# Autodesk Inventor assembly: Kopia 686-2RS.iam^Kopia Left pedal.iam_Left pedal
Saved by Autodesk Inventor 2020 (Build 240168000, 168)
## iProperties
Created: 2017-10
Part Number: Kopia 686-2RS.iam^Kopia Left pedal.iam_Left pedal
Material: Ogólny
Document SubType Name: Assembly
Designer: Tomasz
Sending System: SolidWorks 2017
Last Author: Tomasz
Last Saved: 2017-11-20
Author: Tomasz
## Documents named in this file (13)
- C:\Users\bruno\Documents\1-Cours-2020-21\1STI2D-2020-21\IT\6. Antivol\Inventor-Antivol\INVENTOR 2018_Steel Hardtail B+\Kopia 686-2RS.iam^Kopia Left pedal.iam_Left pedal.iam
- C:\Users\bruno\Documents\1-Cours-2020-21\1STI2D-2020-21\IT\6. Antivol\Inventor-Antivol\INVENTOR 2018_Steel Hardtail B+\Kopia 686-2Z_12.ipt^Kopia 686-2RS.iam_Kopia Left pedal.iam_Left pedal.ipt
- C:\Users\bruno\Documents\1-Cours-2020-21\1STI2D-2020-21\IT\6. Antivol\Inventor-Antivol\INVENTOR 2018_Steel Hardtail B+\Kopia 686-2Z_11.ipt^Kopia 686-2RS.iam_Kopia Left pedal.iam_Left pedal.ipt
- C:\Users\bruno\Documents\1-Cours-2020-21\1STI2D-2020-21\IT\6. Antivol\Inventor-Antivol\INVENTOR 2018_Steel Hardtail B+\Kopia 686-2Z_10.ipt^Kopia 686-2RS.iam_Kopia Left pedal.iam_Left pedal.ipt
- C:\Users\bruno\Documents\1-Cours-2020-21\1STI2D-2020-21\IT\6. Antivol\Inventor-Antivol\INVENTOR 2018_Steel Hardtail B+\Kopia 686-2Z_09.ipt^Kopia 686-2RS.iam_Kopia Left pedal.iam_Left pedal.ipt
- C:\Users\bruno\Documents\1-Cours-2020-21\1STI2D-2020-21\IT\6. Antivol\Inventor-Antivol\INVENTOR 2018_Steel Hardtail B+\Kopia 686-2Z_08.ipt^Kopia 686-2RS.iam_Kopia Left pedal.iam_Left pedal.ipt
- C:\Users\bruno\Documents\1-Cours-2020-21\1STI2D-2020-21\IT\6. Antivol\Inventor-Antivol\INVENTOR 2018_Steel Hardtail B+\Kopia 686-2Z_07.ipt^Kopia 686-2RS.iam_Kopia Left pedal.iam_Left pedal.ipt
- C:\Users\bruno\Documents\1-Cours-2020-21\1STI2D-2020-21\IT\6. Antivol\Inventor-Antivol\INVENTOR 2018_Steel Hardtail B+\Kopia 686-2Z_06.ipt^Kopia 686-2RS.iam_Kopia Left pedal.iam_Left pedal.ipt
- C:\Users\bruno\Documents\1-Cours-2020-21\1STI2D-2020-21\IT\6. Antivol\Inventor-Antivol\INVENTOR 2018_Steel Hardtail B+\Kopia 686-2Z_05.ipt^Kopia 686-2RS.iam_Kopia Left pedal.iam_Left pedal.ipt
- C:\Users\bruno\Documents\1-Cours-2020-21\1STI2D-2020-21\IT\6. Antivol\Inventor-Antivol\INVENTOR 2018_Steel Hardtail B+\Kopia 686-2Z_04.ipt^Kopia 686-2RS.iam_Kopia Left pedal.iam_Left pedal.ipt
- C:\Users\bruno\Documents\1-Cours-2020-21\1STI2D-2020-21\IT\6. Antivol\Inventor-Antivol\INVENTOR 2018_Steel Hardtail B+\Kopia 686-2Z_03.ipt^Kopia 686-2RS.iam_Kopia Left pedal.iam_Left pedal.ipt
- C:\Users\bruno\Documents\1-Cours-2020-21\1STI2D-2020-21\IT\6. Antivol\Inventor-Antivol\INVENTOR 2018_Steel Hardtail B+\Kopia 686-2Z_02.ipt^Kopia 686-2RS.iam_Kopia Left pedal.iam_Left pedal.ipt
- C:\Users\bruno\Documents\1-Cours-2020-21\1STI2D-2020-21\IT\6. Antivol\Inventor-Antivol\INVENTOR 2018_Steel Hardtail B+\Kopia 686-2Z_01.ipt^Kopia 686-2RS.iam_Kopia Left pedal.iam_Left pedal.ipt
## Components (12 placed, 12 different names)
1. Kopia 686-2Z_12.ipt^Kopia 686-2RS.iam_Kopia Left pedal.iam_Left pedal:1
2. Kopia 686-2Z_11.ipt^Kopia 686-2RS.iam_Kopia Left pedal.iam_Left pedal:1
3. Kopia 686-2Z_10.ipt^Kopia 686-2RS.iam_Kopia Left pedal.iam_Left pedal:1
4. Kopia 686-2Z_09.ipt^Kopia 686-2RS.iam_Kopia Left pedal.iam_Left pedal:1
5. Kopia 686-2Z_08.ipt^Kopia 686-2RS.iam_Kopia Left pedal.iam_Left pedal:1
6. Kopia 686-2Z_07.ipt^Kopia 686-2RS.iam_Kopia Left pedal.iam_Left pedal:1
7. Kopia 686-2Z_06.ipt^Kopia 686-2RS.iam_Kopia Left pedal.iam_Left pedal:1
8. Kopia 686-2Z_05.ipt^Kopia 686-2RS.iam_Kopia Left pedal.iam_Left pedal:1
9. Kopia 686-2Z_04.ipt^Kopia 686-2RS.iam_Kopia Left pedal.iam_Left pedal:1
10. Kopia 686-2Z_03.ipt^Kopia 686-2RS.iam_Kopia Left pedal.iam_Left pedal:1
11. Kopia 686-2Z_02.ipt^Kopia 686-2RS.iam_Kopia Left pedal.iam_Left pedal:1
12. Kopia 686-2Z_01.ipt^Kopia 686-2RS.iam_Kopia Left pedal.iam_Left pedal:1
